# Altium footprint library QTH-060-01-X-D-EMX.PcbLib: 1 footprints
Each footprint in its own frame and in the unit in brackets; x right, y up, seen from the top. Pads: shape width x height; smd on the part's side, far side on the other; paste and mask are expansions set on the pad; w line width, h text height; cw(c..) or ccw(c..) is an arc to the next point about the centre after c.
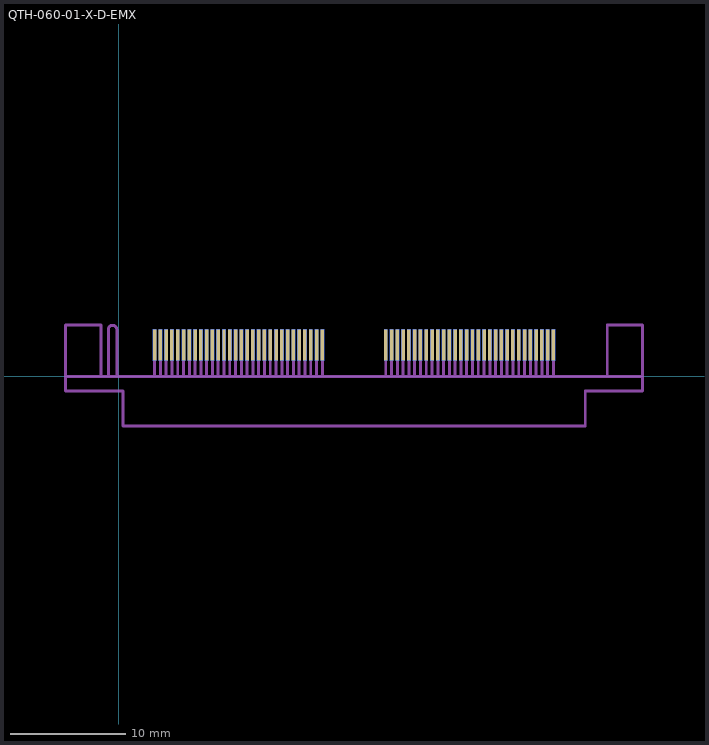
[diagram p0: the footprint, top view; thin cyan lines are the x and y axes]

## QTH-060-01-X-D-EMX [mm] "0.50mm pitch, 120 pin, connector, w/edge mounts"
height 3.62
pads (120):
  rect 0.3x2.7 smd mask+0: 1(3.091,2.73) 3(3.592,2.73) 5(4.092,2.73) 7(4.592,2.73) 9(5.093,2.73) 11(5.593,2.73) 13(6.093,2.73) 15(6.594,2.73) 17(7.094,2.73) 19(7.595,2.73) 21(8.095,2.73) 23(8.595,2.73) 25(9.096,2.73) 27(9.596,2.73) 29(10.096,2.73) 31(10.597,2.73) 33(11.097,2.73) 35(11.598,2.73) 37(12.098,2.73) 39(12.598,2.73) 41(13.099,2.73) 43(13.599,2.73) 45(14.1,2.73) 47(14.6,2.73) 49(15.1,2.73) 51(15.601,2.73) 53(16.101,2.73) 55(16.601,2.73) 57(17.102,2.73) 59(17.602,2.73) 61(23.094,2.73) 63(23.594,2.73) 65(24.094,2.73) 67(24.595,2.73) 69(25.095,2.73) 71(25.596,2.73) 73(26.096,2.73) 75(26.596,2.73) 77(27.097,2.73) 79(27.597,2.73) 81(28.097,2.73) 83(28.598,2.73) 85(29.098,2.73) 87(29.599,2.73) 89(30.099,2.73) 91(30.599,2.73) 93(31.1,2.73) 95(31.6,2.73) 97(32.101,2.73) 99(32.601,2.73) 101(33.101,2.73) 103(33.602,2.73) 105(34.102,2.73) 107(34.602,2.73) 109(35.103,2.73) 111(35.603,2.73) 113(36.104,2.73) 115(36.604,2.73) 117(37.104,2.73) 119(37.605,2.73)
  rect 0.3x2.7 smd far side mask+0: 2(3.091,2.73) 4(3.592,2.73) 6(4.092,2.73) 8(4.592,2.73) 10(5.093,2.73) 12(5.593,2.73) 14(6.093,2.73) 16(6.594,2.73) 18(7.094,2.73) 20(7.595,2.73) 22(8.095,2.73) 24(8.595,2.73) 26(9.096,2.73) 28(9.596,2.73) 30(10.096,2.73) 32(10.597,2.73) 34(11.097,2.73) 36(11.598,2.73) 38(12.098,2.73) 40(12.598,2.73) 42(13.099,2.73) 44(13.599,2.73) 46(14.1,2.73) 48(14.6,2.73) 50(15.1,2.73) 52(15.601,2.73) 54(16.101,2.73) 56(16.601,2.73) 58(17.102,2.73) 60(17.602,2.73) 62(23.094,2.73) 64(23.594,2.73) 66(24.094,2.73) 68(24.595,2.73) 70(25.095,2.73) 72(25.596,2.73) 74(26.096,2.73) 76(26.596,2.73) 78(27.097,2.73) 80(27.597,2.73) 82(28.097,2.73) 84(28.598,2.73) 86(29.098,2.73) 88(29.599,2.73) 90(30.099,2.73) 92(30.599,2.73) 94(31.1,2.73) 96(31.6,2.73) 98(32.101,2.73) 100(32.601,2.73) 102(33.101,2.73) 104(33.602,2.73) 106(34.102,2.73) 108(34.602,2.73) 110(35.103,2.73) 112(35.603,2.73) 114(36.104,2.73) 116(36.604,2.73) 118(37.104,2.73) 120(37.605,2.73)
Top Solder:
  lines w0.127: 3.091,2.896 3.091,4.064 ; 3.592,2.896 3.592,4.064 ; 4.092,2.896 4.092,4.064 ; 4.592,2.896 4.592,4.064 ; 5.093,2.896 5.093,4.064 ; 5.593,2.896 5.593,4.064 ; 6.093,2.896 6.093,4.064 ; 6.594,2.896 6.594,4.064 ; 7.094,2.896 7.094,4.064 ; 7.595,2.896 7.595,4.064 ; 8.095,2.896 8.095,4.064 ; 8.595,2.896 8.595,4.064 ; 9.096,2.896 9.096,4.064 ; 9.596,2.896 9.596,4.064 ; 10.096,2.896 10.096,4.064 ; 10.597,2.896 10.597,4.064 ; 11.097,2.896 11.097,4.064 ; 11.598,2.896 11.598,4.064 ; 12.098,2.896 12.098,4.064 ; 12.598,2.896 12.598,4.064 ; 13.099,2.896 13.099,4.064 ; 13.599,2.896 13.599,4.064 ; 14.1,2.896 14.1,4.064 ; 14.6,2.896 14.6,4.064 ; 15.1,2.896 15.1,4.064 ; 15.601,2.896 15.601,4.064 ; 16.101,2.896 16.101,4.064 ; 16.601,2.896 16.601,4.064 ; 17.102,2.896 17.102,4.064 ; 17.602,2.896 17.602,4.064 ; 23.094,2.896 23.094,4.064 ; 23.594,2.896 23.594,4.064 ; 24.094,2.896 24.094,4.064 ; 24.595,2.896 24.595,4.064 ; 25.095,2.896 25.095,4.064 ; 25.596,2.896 25.596,4.064 ; 26.096,2.896 26.096,4.064 ; 26.596,2.896 26.596,4.064 ; 27.097,2.896 27.097,4.064 ; 27.597,2.896 27.597,4.064 ; 28.097,2.896 28.097,4.064 ; 28.598,2.896 28.598,4.064 ; 29.098,2.896 29.098,4.064 ; 29.599,2.896 29.599,4.064 ; 30.099,2.896 30.099,4.064 ; 30.599,2.896 30.599,4.064 ; 31.1,2.896 31.1,4.064 ; 31.6,2.896 31.6,4.064 ; 32.101,2.896 32.101,4.064 ; 32.601,2.896 32.601,4.064 ; 33.101,2.896 33.101,4.064 ; 33.602,2.896 33.602,4.064 ; 34.102,2.896 34.102,4.064 ; 34.602,2.896 34.602,4.064 ; 35.103,2.896 35.103,4.064 ; 35.603,2.896 35.603,4.064 ; 36.104,2.896 36.104,4.064 ; 36.604,2.896 36.604,4.064 ; 37.104,2.896 37.104,4.064 ; 37.605,2.896 37.605,4.064
Bottom Solder:
  lines w0.127: 3.091,2.896 3.091,4.064 ; 3.592,2.896 3.592,4.064 ; 4.092,2.896 4.092,4.064 ; 4.592,2.896 4.592,4.064 ; 5.093,2.896 5.093,4.064 ; 5.593,2.896 5.593,4.064 ; 6.093,2.896 6.093,4.064 ; 6.594,2.896 6.594,4.064 ; 7.094,2.896 7.094,4.064 ; 7.595,2.896 7.595,4.064 ; 8.095,2.896 8.095,4.064 ; 8.595,2.896 8.595,4.064 ; 9.096,2.896 9.096,4.064 ; 9.596,2.896 9.596,4.064 ; 10.096,2.896 10.096,4.064 ; 10.597,2.896 10.597,4.064 ; 11.097,2.896 11.097,4.064 ; 11.598,2.896 11.598,4.064 ; 12.098,2.896 12.098,4.064 ; 12.598,2.896 12.598,4.064 ; 13.099,2.896 13.099,4.064 ; 13.599,2.896 13.599,4.064 ; 14.1,2.896 14.1,4.064 ; 14.6,2.896 14.6,4.064 ; 15.1,2.896 15.1,4.064 ; 15.601,2.896 15.601,4.064 ; 16.101,2.896 16.101,4.064 ; 16.601,2.896 16.601,4.064 ; 17.102,2.896 17.102,4.064 ; 17.602,2.896 17.602,4.064 ; 23.094,2.896 23.094,4.064 ; 23.594,2.896 23.594,4.064 ; 24.094,2.896 24.094,4.064 ; 24.595,2.896 24.595,4.064 ; 25.095,2.896 25.095,4.064 ; 25.596,2.896 25.596,4.064 ; 26.096,2.896 26.096,4.064 ; 26.596,2.896 26.596,4.064 ; 27.097,2.896 27.097,4.064 ; 27.597,2.896 27.597,4.064 ; 28.097,2.896 28.097,4.064 ; 28.598,2.896 28.598,4.064 ; 29.098,2.896 29.098,4.064 ; 29.599,2.896 29.599,4.064 ; 30.099,2.896 30.099,4.064 ; 30.599,2.896 30.599,4.064 ; 31.1,2.896 31.1,4.064 ; 31.6,2.896 31.6,4.064 ; 32.101,2.896 32.101,4.064 ; 32.601,2.896 32.601,4.064 ; 33.101,2.896 33.101,4.064 ; 33.602,2.896 33.602,4.064 ; 34.102,2.896 34.102,4.064 ; 34.602,2.896 34.602,4.064 ; 35.103,2.896 35.103,4.064 ; 35.603,2.896 35.603,4.064 ; 36.104,2.896 36.104,4.064 ; 36.604,2.896 36.604,4.064 ; 37.104,2.896 37.104,4.064 ; 37.605,2.896 37.605,4.064
Mechanical 2:
  lines w0.254: -4.597,0 -1.575,0 ; -0.914,0 -0.914,4.064 cw(c-0.546,4.064) -0.178,4.064 -0.178,0 ; 3.091,0 3.091,2.794 ; 3.592,0 3.592,2.794 ; 4.092,0 4.092,2.794 ; 4.592,0 4.592,2.794 ; 5.093,0 5.093,2.794 ; 5.593,0 5.593,2.794 ; 6.093,0 6.093,2.794 ; 6.594,0 6.594,2.794 ; 7.094,0 7.094,2.794 ; 7.595,0 7.595,2.794 ; 8.095,0 8.095,2.794 ; 8.595,0 8.595,2.794 ; 9.096,0 9.096,2.794 ; 9.596,0 9.596,2.794 ; 10.096,0 10.096,2.794 ; 10.597,0 10.597,2.794 ; 11.097,0 11.097,2.794 ; 11.598,0 11.598,2.794 ; 12.098,0 12.098,2.794 ; 12.598,0 12.598,2.794 ; 13.099,0 13.099,2.794 ; 13.599,0 13.599,2.794 ; 14.1,0 14.1,2.794 ; 14.6,0 14.6,2.794 ; 15.1,0 15.1,2.794 ; 15.601,0 15.601,2.794 ; 16.101,0 16.101,2.794 ; 16.601,0 16.601,2.794 ; 17.102,0 17.102,2.794 ; 17.602,0 17.602,2.794 ; 23.094,0 23.094,2.794 ; 23.594,0 23.594,2.794 ; 24.094,0 24.094,2.794 ; 24.595,0 24.595,2.794 ; 25.095,0 25.095,2.794 ; 25.596,0 25.596,2.794 ; 26.096,0 26.096,2.794 ; 26.596,0 26.596,2.794 ; 27.097,0 27.097,2.794 ; 27.597,0 27.597,2.794 ; 28.097,0 28.097,2.794 ; 28.598,0 28.598,2.794 ; 29.098,0 29.098,2.794 ; 29.599,0 29.599,2.794 ; 30.099,0 30.099,2.794 ; 30.599,0 30.599,2.794 ; 31.1,0 31.1,2.794 ; 31.6,0 31.6,2.794 ; 32.101,0 32.101,2.794 ; 32.601,0 32.601,2.794 ; 33.101,0 33.101,2.794 ; 33.602,0 33.602,2.794 ; 34.102,0 34.102,2.794 ; 34.602,0 34.602,2.794 ; 35.103,0 35.103,2.794 ; 35.603,0 35.603,2.794 ; 36.104,0 36.104,2.794 ; 36.604,0 36.604,2.794 ; 37.104,0 37.104,2.794 ; 37.605,0 37.605,2.794 ; 42.278,0 45.301,0 ; -4.614,-1.27 -4.614,4.445 -1.566,4.445 -1.566,0 42.262,0 42.262,4.445 45.31,4.445 45.31,-1.27 40.357,-1.27 40.357,-4.267 0.339,-4.267 0.339,-1.27 -4.614,-1.27
Mechanical 13:
  lines w0.1: -4.597,0 -1.575,0 ; -0.914,0 -0.914,4.064 cw(c-0.546,4.064) -0.178,4.064 -0.178,0 ; 3.091,0 3.091,2.794 ; 3.592,0 3.592,2.794 ; 4.092,0 4.092,2.794 ; 4.592,0 4.592,2.794 ; 5.093,0 5.093,2.794 ; 5.593,0 5.593,2.794 ; 6.093,0 6.093,2.794 ; 6.594,0 6.594,2.794 ; 7.094,0 7.094,2.794 ; 7.595,0 7.595,2.794 ; 8.095,0 8.095,2.794 ; 8.595,0 8.595,2.794 ; 9.096,0 9.096,2.794 ; 9.596,0 9.596,2.794 ; 10.096,0 10.096,2.794 ; 10.597,0 10.597,2.794 ; 11.097,0 11.097,2.794 ; 11.598,0 11.598,2.794 ; 12.098,0 12.098,2.794 ; 12.598,0 12.598,2.794 ; 13.099,0 13.099,2.794 ; 13.599,0 13.599,2.794 ; 14.1,0 14.1,2.794 ; 14.6,0 14.6,2.794 ; 15.1,0 15.1,2.794 ; 15.601,0 15.601,2.794 ; 16.101,0 16.101,2.794 ; 16.601,0 16.601,2.794 ; 17.102,0 17.102,2.794 ; 17.602,0 17.602,2.794 ; 23.094,0 23.094,2.794 ; 23.594,0 23.594,2.794 ; 24.094,0 24.094,2.794 ; 24.595,0 24.595,2.794 ; 25.095,0 25.095,2.794 ; 25.596,0 25.596,2.794 ; 26.096,0 26.096,2.794 ; 26.596,0 26.596,2.794 ; 27.097,0 27.097,2.794 ; 27.597,0 27.597,2.794 ; 28.097,0 28.097,2.794 ; 28.598,0 28.598,2.794 ; 29.098,0 29.098,2.794 ; 29.599,0 29.599,2.794 ; 30.099,0 30.099,2.794 ; 30.599,0 30.599,2.794 ; 31.1,0 31.1,2.794 ; 31.6,0 31.6,2.794 ; 32.101,0 32.101,2.794 ; 32.601,0 32.601,2.794 ; 33.101,0 33.101,2.794 ; 33.602,0 33.602,2.794 ; 34.102,0 34.102,2.794 ; 34.602,0 34.602,2.794 ; 35.103,0 35.103,2.794 ; 35.603,0 35.603,2.794 ; 36.104,0 36.104,2.794 ; 36.604,0 36.604,2.794 ; 37.104,0 37.104,2.794 ; 37.605,0 37.605,2.794 ; 42.278,0 45.301,0 ; -4.614,-1.27 -4.614,4.445 -1.566,4.445 -1.566,0 42.262,0 42.262,4.445 45.31,4.445 45.31,-1.27 40.357,-1.27 40.357,-4.267 0.339,-4.267 0.339,-1.27 -4.614,-1.27
  text ".Designator" at 0,0 h1.52
Drill Drawing:
  lines w0.01: -7.188,0 -1.092,0 -1.092,4.153 cw(c-0.546,4.153) 0,4.153 0,0 47.879,0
